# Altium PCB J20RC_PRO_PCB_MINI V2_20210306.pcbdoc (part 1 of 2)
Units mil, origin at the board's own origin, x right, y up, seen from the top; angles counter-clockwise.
Board outline 5082.94 x 4658.14 mil, 2 copper layers (Top Layer, Bottom Layer); 108 components, 96 nets, 409 pads, 123 vias.
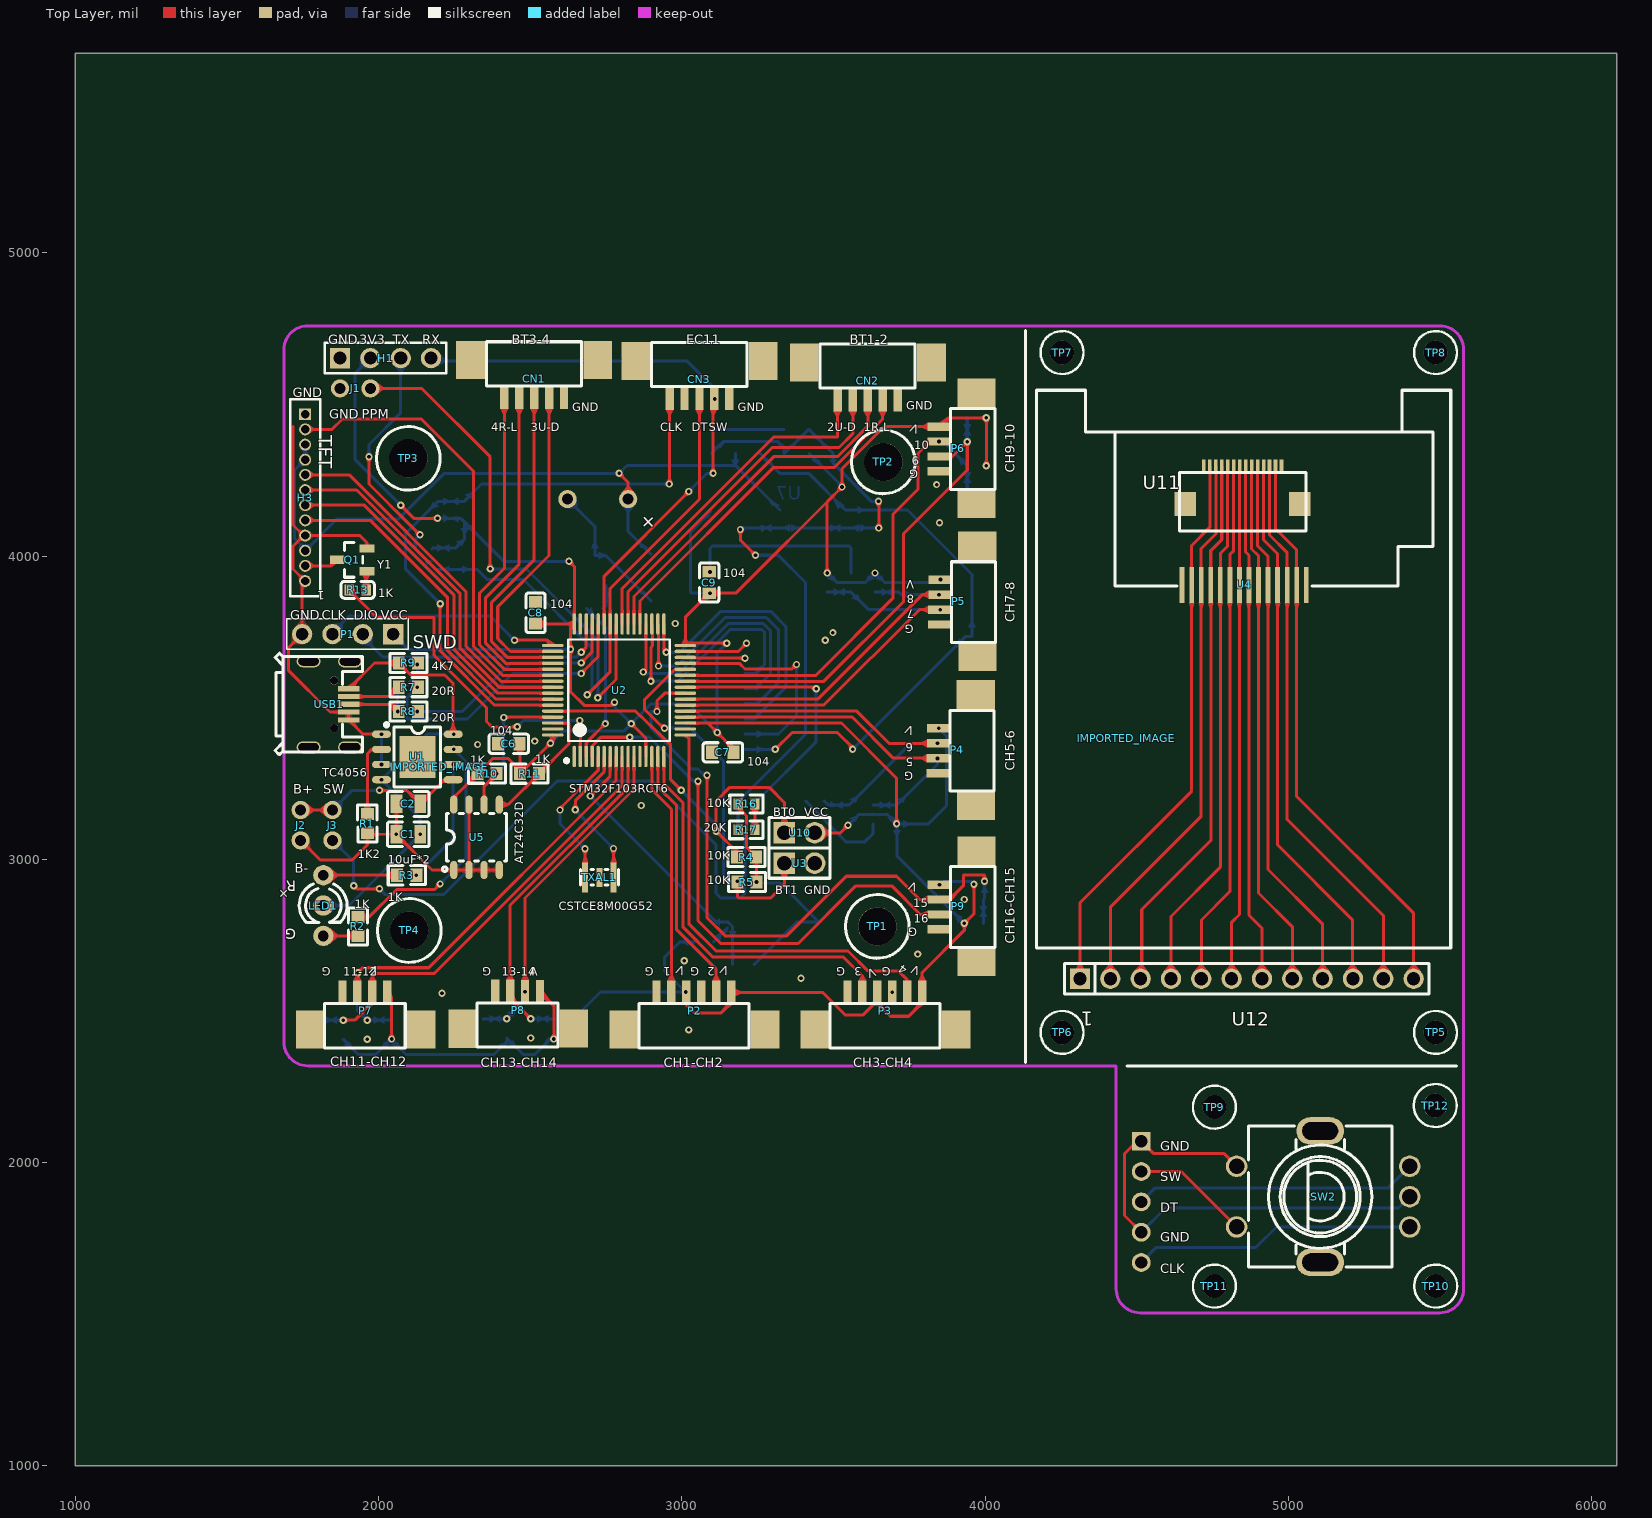
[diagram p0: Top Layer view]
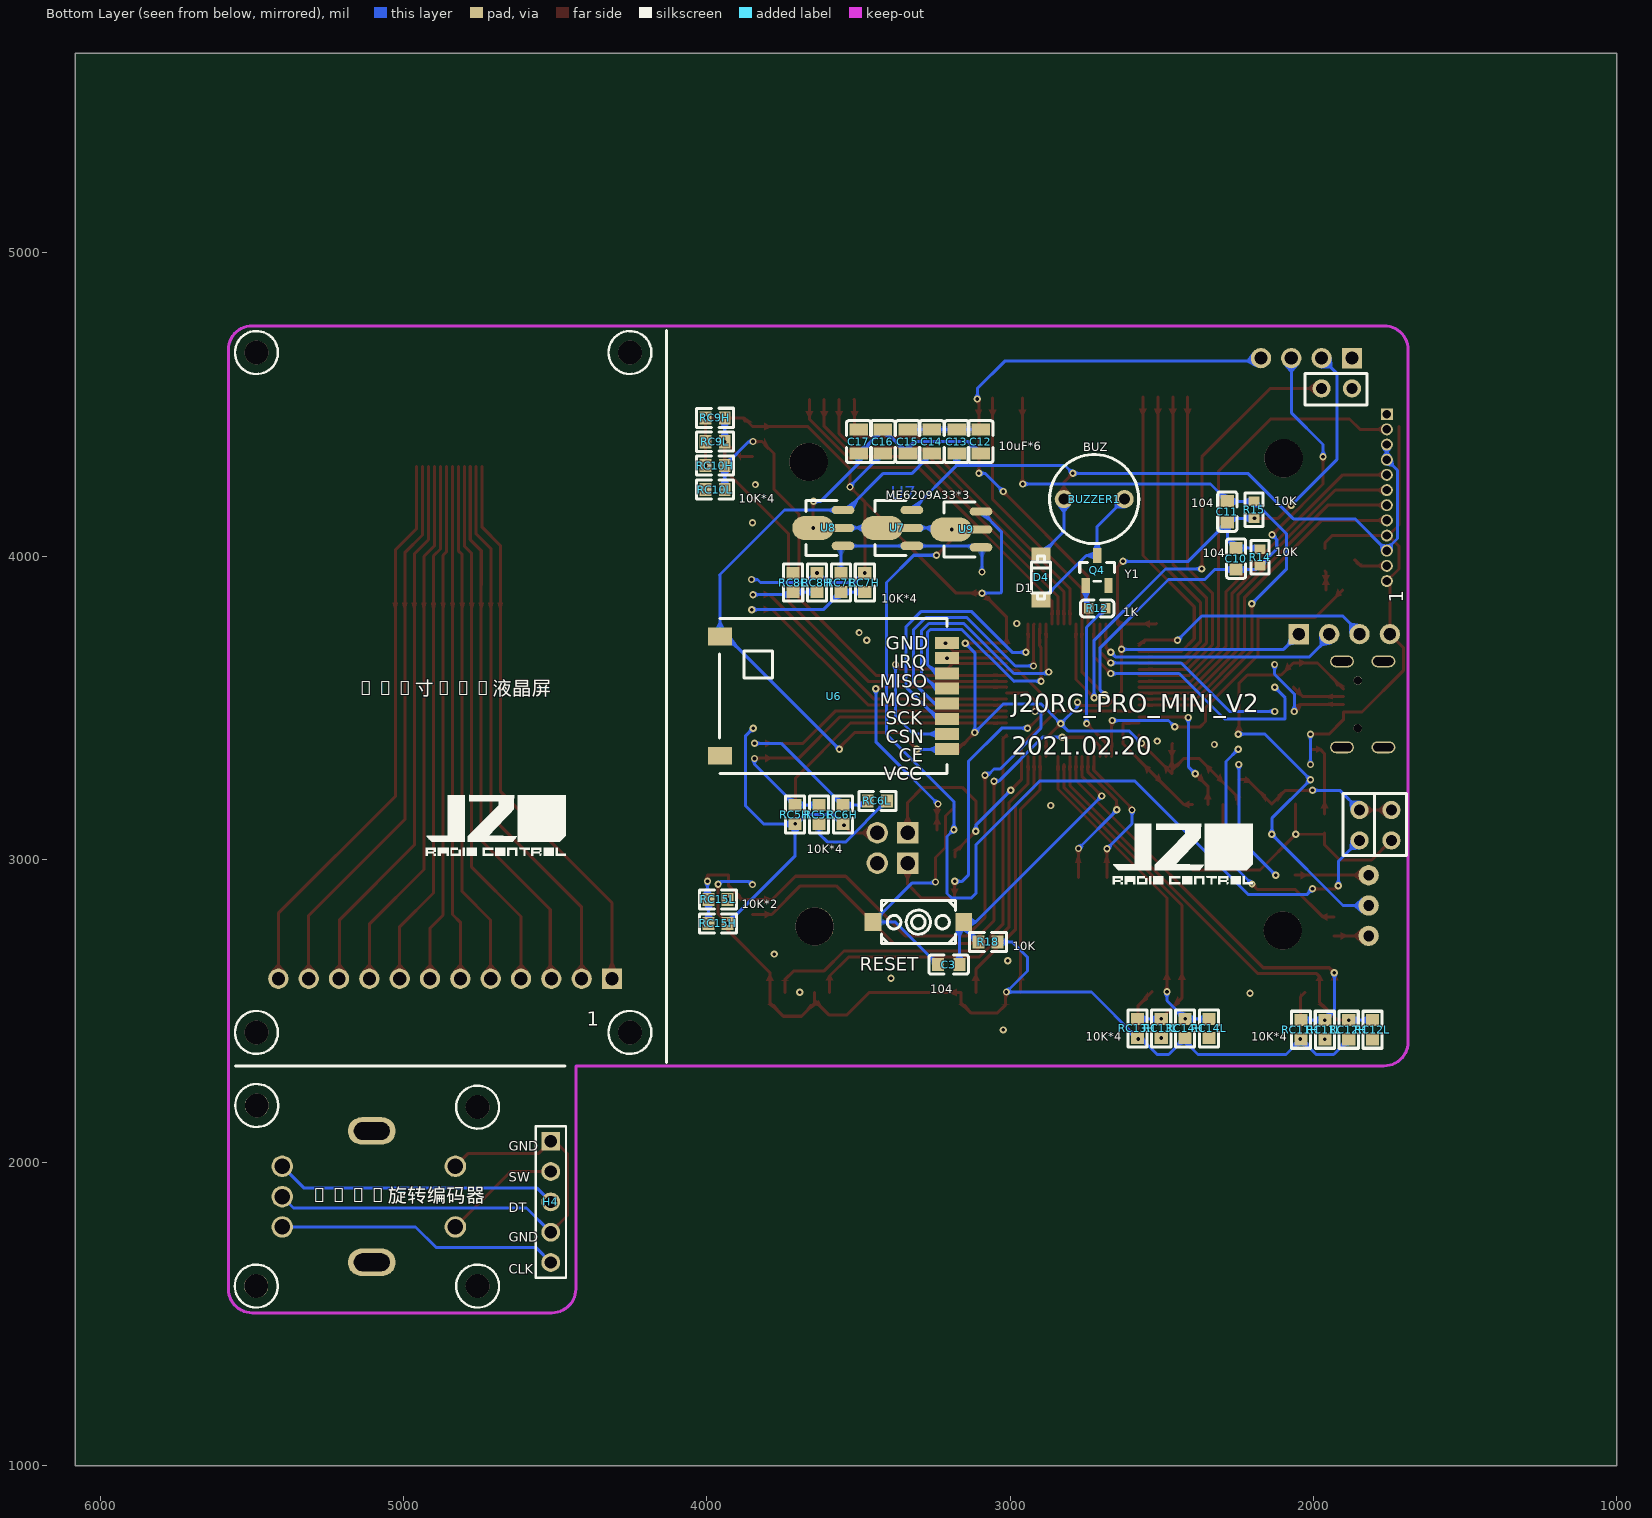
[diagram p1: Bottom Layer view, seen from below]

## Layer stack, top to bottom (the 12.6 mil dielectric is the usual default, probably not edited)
Top Layer: signal copper (thickness not stored)
Dielectric: dielectric 12.6, FR-4, Dk 4.8
Bottom Layer: signal copper (thickness not stored)

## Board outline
6082.94,1000 1000,1000 1000,5658.14 6082.94,5658.14

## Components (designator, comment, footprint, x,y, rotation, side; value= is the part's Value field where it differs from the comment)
BUZZER1 "CY-9650-5029" 3.3V蜂鸣器 2823.27,4187.75 r0 bottom
C1 "10uF" C0805#1 2098.27,3082.75 r180 top
C2 "10uF" C0805#1 2098.27,3182.75 r0 top
C3 "104" C0603#1 3202.95,2653.07 r180 bottom
C6 "104" C0603#2 2429.92,3381.37 r0 top
C7 "104" C0603#2 3135.43,3353.03 r0 top
C8 "104" C0603#2 2518.11,3812.87 r270 top
C9 "104" C0603#2 3090.55,3912.87 r270 top
C10 "104" C0603#1 2255.12,3991.61 r270 bottom
C11 "104" C0603#1 2284.25,4146.73 r270 bottom
C12 "10uF" C0805#2 3097.64,4377.44 r90 bottom
C13 "10uF" C0805#2 3176.38,4377.44 r90 bottom
C14 "10uF" C0805#2 3259.06,4377.44 r90 bottom
C15 "10uF" C0805#2 3337.8,4377.44 r90 bottom
C16 "10uF" C0805#2 3420.47,4377.44 r90 bottom
C17 "10uF" C0805#2 3499.21,4377.44 r90 bottom
CN1 "1.25T-5P" CONN-SMD_1.25T-5P 2513.27,4585.25 r0 top
CN2 "1.25T-5P" CONN-SMD_1.25T-5P 3613.27,4577.75 r0 top
CN3 "1.25T-5P" CONN-SMD_1.25T-5P 3058.27,4582.75 r0 top
D4 "1N5819" 1N5819-SOD123 2893.27,3947.75 r0 bottom
H1 "A2541WV-4P" HDR-TH_4P-P2.54-V 2023.27,4652.75 r0 top
H3 "1.27mm1*12P Straight Headers  Pins" HDR-TH_12P-P1.27-V 1758.27,4192.75 r270 top
H4 "HDR-TH_5P-P2.54-V" HDR-TH_5P-P2.54-V 4514.78,1870.81 r90 bottom
IMPORTED_IMAGE "IMPORTED_IMAGE" IMPORTED_IMAGE 2200,3305.15 r0 top
IMPORTED_IMAGE "IMPORTED_IMAGE" IMPORTED_IMAGE 4464.89,3399.2 r0 top
J1 "PPM接口" 2.54MM_2P 1873.27,4552.75 r270 top
J2 "电池" 2.54MM_2P 1743.27,3062.75 r0 top
J3 "PPM接口" 2.54MM_2P 1848.27,3062.75 r0 top
LED1 "5mm双色LED共阳极" 3MM双色LED共阳极 1818.27,2847.75 r270 top
P1 "SWD接口" 4P_2.54 1903.27,3737.75 r0 top
P2 "CH1-2" 1.25MM-6P 3138.56,2500.25 r180 top
P3 "CH3-4" 1.25MM-6P 3768.27,2500.25 r180 top
P4 "CH5-6" 1.25MM-4P 3908.27,3407.75 r270 top
P5 "CH7-8" 1.25MM-4P 3913.27,3897.75 r270 top
P6 "CH7-8" 1.25MM-4P 3910.77,4402.75 r270 top
P7 "CH5-6" 1.25MM-4P 2004.72,2500.27 r180 top
P8 "CH7-8" 1.25MM-4P 2508.27,2502.75 r180 top
P9 "CH5-6" 1.25MM-4P 3910.77,2892.75 r270 top
Q1 "SS8050" SOT-23(SOT-23-3)#1 1913.27,3987.75 r90 top
Q4 "SS8050" SOT-23(SOT-23-3)#2 2713.27,3952.75 r0 bottom
R1 "1.2k" R0603#1 1963.27,3117.75 r90 top
R2 "1k" R0603#1 1932.28,2779.01 r90 top
R3 "1k" R0603#1 2093.27,2947.75 r0 top
R4 "10k" R0603#1 3213.27,3007.75 r0 top
R5 "10k" R0603#1 3214.71,2925.35 r0 top
R7 "20R" R0603#1 2098.27,3567.75 r180 top
R8 "20R" R0603#1 2098.27,3487.75 r180 top
R9 "4.7k" R0603#1 2098.27,3647.75 r0 top
R10 "1k" R0603#1 2358.27,3282.75 r180 top
R11 "1k" R0603#1 2498.27,3282.75 r180 top
R12 "1k" C0603#3 2713.27,3827.75 r180 bottom
R13 "1k" C0603#4 1931.51,3888.42 r0 top
R14 "10k" R0603#2 2176.38,3995.55 r90 bottom
R15 "10k" R0603#2 2196.06,4153.03 r90 bottom
R16 "10k" R0603#3 3213.27,3182.75 r0 top
R17 "20k" R0603#3 3213.27,3097.75 r180 top
R18 "10k" R0603#4 3073.27,2727.75 r0 bottom
RC5H "10k" R0603#4 3709.29,3147.73 r270 bottom
RC5L "10k" R0603#4 3630.55,3147.73 r270 bottom
RC6H "10k" R0603#4 3551.81,3147.73 r270 bottom
RC6L "10k" R0603#4 3438.27,3192.75 r180 bottom
RC7H "10k" R0603#4 3479.53,3912.75 r90 bottom
RC7L "10k" R0603#4 3558.27,3912.75 r90 bottom
RC8H "10k" R0603#4 3637.01,3912.75 r90 bottom
RC8L "10k" R0603#4 3715.75,3912.75 r90 bottom
RC9H "10k" R0603#4 3972.75,4455.77 r0 bottom
RC9L "10k" R0603#4 3972.75,4377.03 r0 bottom
RC10H "10k" R0603#4 3972.75,4298.29 r0 bottom
RC10L "10k" R0603#4 3972.75,4219.55 r0 bottom
RC11H "10k" R0603#4 2041.29,2438.27 r270 bottom
RC11L "10k" R0603#4 1962.55,2438.27 r270 bottom
RC12H "10k" R0603#4 1883.81,2438.27 r270 bottom
RC12L "10k" R0603#4 1805.07,2438.27 r270 bottom
RC13H "10k" R0603#4 2580.75,2442.75 r270 bottom
RC13L "10k" R0603#4 2502.01,2442.75 r270 bottom
RC14H "10k" R0603#4 2423.27,2442.75 r270 bottom
RC14L "10k" R0603#4 2344.53,2442.75 r270 bottom
RC15H "10k" R0603#4 3963.27,2789.01 r180 bottom
RC15L "10k" R0603#4 3963.27,2867.75 r180 bottom
RESET "K2-3.6×6.1_SMD" KEY-SMD_2P-L6.2-W3.6-LS8.0 3302.97,2793.05 r180 bottom
SW2 "EC11" SW-TH_EC11XXXXXXXX 5114.78,1888.01 r90 top
TP1 "M3铜柱_LCEDA" M3铜柱_LCEDA 3644.88,2779.01 r0 top
TP2 "M3铜柱_LCEDA" M3铜柱_LCEDA 3664.57,4310.51 r0 top
TP3 "M3铜柱_LCEDA" M3铜柱_LCEDA 2098.42,4322.32 r0 top
TP4 "M3铜柱_LCEDA" M3铜柱_LCEDA 2101.57,2765.63 r0 top
TP5 "M2铜柱" M2铜柱 5485.23,2429.41 r0 top
TP6 "M2铜柱" M2铜柱 4253.73,2429.41 r0 top
TP7 "M2铜柱" M2铜柱 4253.74,4671.14 r0 top
TP8 "M2铜柱" M2铜柱 5485.23,4671.14 r0 top
TP9 "M2铜柱" M2铜柱 4756.12,2183.12 r0 top
TP10 "M2铜柱" M2铜柱 5485.82,1593.19 r0 top
TP11 "M2铜柱" M2铜柱 4756.12,1593.19 r0 top
TP12 "M2铜柱" M2铜柱 5484.24,2188.46 r0 top
TXAL1 "OSC-SMD_3P-L3.2-W1.3-P1.2-L" OSC-SMD_3P-L3.2-W1.3-P1.2-L 2728.34,2940.43 r0 top
U1 "TC4056A" SOP-8_L4.9-W3.9-P1.27-LS6.0-BL-EP 2128.27,3337.75 r270 top
U2 "STM32F103RCT6" LQFP-64_L10.0-W10.0-P0.50-LS12.0-BL 2793.27,3557.75 r0 top
U3 "插排1*2P2.54mm" 1*2P-P2.54插针 3388.27,2987.75 r0 top
U4 "1.8寸TFTLCD" 1.8_TFT_LCD 4854.36,3838.14 r180 top
U5 "AT24C32D" SOIC-8_L4.9-W3.9-P1.27-LS6.0-BL 2323.27,3072.75 r0 top
U6 "NRF24L01" NRF24L01 3208.27,3282.75 r180 bottom
U7 "ME6209A33PG" SOT-89-3_L4.5-W2.5-P1.50-LS4.2-BR 3373.27,4092.75 r0 bottom
U8 "ME6209A33PG" SOT-89-3_L4.5-W2.5-P1.50-LS4.2-BR 3600.56,4092.75 r0 bottom
U9 "ME6209A33PG" SOT-89-3_L4.5-W2.5-P1.50-LS4.2-BR 3145.56,4087.75 r0 bottom
U10 "插排1*2P2.54mm" 1*2P-P2.54插针 3388.27,3087.75 r0 top
U11 "1.8寸TFTLCD插座" FPC-0.5MM-14P-QCHF-SM-H2.0 4849.36,4233.14 r0 top
U12 "DIP-1X12P-2.54MM" DIP-1X12P-2.54MM 4962.99,2606.57 r0 top
USB1 "U-F-M5DD-Y-1" MICRO-USB-SMD_U-F-M5DD-Y-1 1837.8,3511.3 r180 top
? "" ? 2880.52,5033.35 r0 top

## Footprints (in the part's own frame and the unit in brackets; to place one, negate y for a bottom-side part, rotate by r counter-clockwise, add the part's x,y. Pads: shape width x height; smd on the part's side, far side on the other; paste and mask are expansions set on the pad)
1*2P-P2.54插针 [mm]
  rect 1.8x1.8 hole 1.2: 1(-1.27,0)
  round 1.8 hole 1.2: 2(1.27,0)
  silkscreen extent -2.54,-1.27 2.54,1.27
1.8_TFT_LCD [mm]
  rect 0.4x3 smd: 1(5.2,-1.7) 2(4.4,-1.7) 3(3.6,-1.7) 4(2.8,-1.7) 5(2,-1.7) 6(1.2,-1.7) 7(0.4,-1.7) 8(-0.4,-1.7) 9(-1.2,-1.7) 10(-2,-1.7) 11(-2.8,-1.7) 12(-3.6,-1.7) 13(-4.4,-1.7) 14(-5.2,-1.7)
  silkscreen extent -17.3,-18 17.4,28.7
1.25MM-4P [mm]
  rect 2.4x3.2 smd: 0(-3.457,1.544) 0(5.845,1.559)
  rect 0.7x2 smd: 1(-0.614,-1.545) 2(0.636,-1.545) 3(1.886,-1.559) 4(3.136,-1.559)
  silkscreen extent -2.12,-0.62 4.65,3.09
1.25MM-6P [mm]
  rect 2.4x3.2 smd: 0(-3.457,1.544) 0(8.362,1.559)
  rect 0.7x2 smd: 1(-0.614,-1.545) 2(0.636,-1.545) 3(1.886,-1.559) 4(3.136,-1.559) 5(4.386,-1.559) 6(5.636,-1.559)
  silkscreen extent -2.12,-0.62 7.1,3.09
1N5819-SOD123 [mil]
  rect 63x43.3 smd: 1(5,95) 2(5,-58.6)
  silkscreen extent -26,-53 36,89
2.54MM_2P [mil]
  round 60 hole 36: 1(0,0) 2(0,100)
3.3V蜂鸣器 [mil]
  round 60 hole 36: 1(0,0) 2(-200,0)
  silkscreen extent -247,-147 47,147
3MM双色LED共阳极 [mm]
  round 1.7 hole 0.9: 1(-2.54,0) 2(0,0) 3(2.54,0)
  silkscreen extent -1.82,-2.02 1.43,1.99
4P_2.54 [mil]
  rect 66.93x66.93 hole 39.36: 1(145,5)
  round 66.93 hole 39.36: 2(45,5) 3(-55,5) 4(-155,5)
  silkscreen extent -205,-45 195,55
C0603#1 [mm]
  rect 1x1.1 smd: 1(0.9,0) 2(-0.9,0)
  silkscreen extent -1.65,-0.8 1.65,0.8
C0603#2 [mm]
  rect 1x1.1 smd: 1(-0.9,0) 2(0.9,0)
  silkscreen extent -1.65,-0.8 1.65,0.8
C0603#3 [mm]
  rect 0.8x0.9 smd: 1(0.7,0) 2(-0.7,0)
  silkscreen extent -1.4,-0.72 1.4,0.7
C0603#4 [mm]
  rect 0.8x0.9 smd: 1(-0.7,0) 2(0.7,0)
  silkscreen extent -1.4,-0.7 1.4,0.72
C0805#1 [mm]
  rect 1x1.55 smd: 1(-1,0) 2(1,0)
  silkscreen extent -1.75,-1.04 1.75,1.04
C0805#2 [mm]
  rect 1x1.55 smd: 1(1,0) 2(-1,0)
  silkscreen extent -1.75,-1.04 1.75,1.04
CONN-SMD_1.25T-5P [mm]
  rect 2.4x3.2 smd: 0(-5.331,1.545) 0(5.331,1.546)
  rect 0.7x2 smd: 1(-2.5,-1.546) 2(-1.25,-1.546) 3(0,-1.546) 4(1.25,-1.546) 5(2.5,-1.546)
  silkscreen extent -4,-0.61 3.96,3.09
DIP-1X12P-2.54MM [mm]
  rect 1.7x1.7 hole 1.1: 1(-16.51,0)
  round 1.7 hole 1.1: 2(-13.97,0) 3(-11.43,0) 4(-8.89,0) 5(-6.35,0) 6(-3.81,0) 7(-1.27,0) 8(1.27,0) 9(3.81,0) 10(6.35,0) 11(8.89,0) 12(11.43,0)
  silkscreen extent -17.82,-1.27 12.7,1.27
FPC-0.5MM-14P-QCHF-SM-H2.0 [mm]
  rect 0.3x1.2 smd: 1(-3.25,1.575) 2(-2.75,1.575) 3(-2.25,1.575) 4(-1.75,1.575) 5(-1.25,1.575) 6(-0.75,1.575) 7(-0.25,1.575) 8(0.25,1.575) 9(0.75,1.575) 10(1.25,1.575) 11(1.75,1.575) 12(2.25,1.575) 13(2.75,1.575) 14(3.25,1.575)
  rect 1.8x2 smd: 15(-4.8,-1.575) 16(4.8,-1.575)
  silkscreen extent -5.3,-3.82 5.3,1.08
HDR-TH_4P-P2.54-V [mm]
  rect 1.7x1.7 hole 1.1: 1(-3.81,0)
  round 1.7 hole 1.1: 2(-1.27,0) 3(1.27,0) 4(3.81,0)
  silkscreen extent -5.08,-1.27 5.08,1.27
HDR-TH_5P-P2.54-V [mil]
  rect 62x62 hole 40.16: 1(200,0)
  round 62 hole 40.16: 2(100,0) 3(0,0) 4(-100,0) 5(-200,0)
  silkscreen extent -250,-50 250,50
HDR-TH_12P-P1.27-V [mm]
  rect 1x1 hole 0.7: 1(-6.985,0)
  round 1 hole 0.7: 2(-5.715,0) 3(-4.445,0) 4(-3.175,0) 5(-1.905,0) 6(-0.635,0) 7(0.635,0) 8(1.905,0) 9(3.175,0) 10(4.445,0) 11(5.715,0) 12(6.985,0)
  silkscreen extent -8.24,-1.25 8.25,1.25
IMPORTED_IMAGE [mil]
KEY-SMD_2P-L6.2-W3.6-LS8.0 [mm]
  rect 1.4x1.5 smd: 1(3.8,0) 2(-3.8,0)
  silkscreen extent -3.1,-1.8 3.1,1.8
LQFP-64_L10.0-W10.0-P0.50-LS12.0-BL [mm]
  oval 0.28x1.8 smd: 1(-3.75,-5.55) 2(-3.25,-5.55) 3(-2.75,-5.55) 4(-2.25,-5.55) 5(-1.75,-5.55) 6(-1.25,-5.55) 7(-0.75,-5.55) 8(-0.25,-5.55) 9(0.25,-5.55) 10(0.75,-5.55) 11(1.25,-5.55) 12(1.75,-5.55) 13(2.25,-5.55) 14(2.75,-5.55) 15(3.25,-5.55) 16(3.75,-5.55) 33(3.75,5.55) 34(3.25,5.55) 35(2.75,5.55) 36(2.25,5.55) 37(1.75,5.55) 38(1.25,5.55) 39(0.75,5.55) 40(0.25,5.55) 41(-0.25,5.55) 42(-0.75,5.55) 43(-1.25,5.55) 44(-1.75,5.55) 45(-2.25,5.55) 46(-2.75,5.55) 47(-3.25,5.55) 48(-3.75,5.55)
  oval 1.8x0.28 smd: 17(5.55,-3.75) 18(5.55,-3.25) 19(5.55,-2.75) 20(5.55,-2.25) 21(5.55,-1.75) 22(5.55,-1.25) 23(5.55,-0.75) 24(5.55,-0.25) 25(5.55,0.25) 26(5.55,0.75) 27(5.55,1.25) 28(5.55,1.75) 29(5.55,2.25) 30(5.55,2.75) 31(5.55,3.25) 32(5.55,3.75) 49(-5.55,3.75) 50(-5.55,3.25) 51(-5.55,2.75) 52(-5.55,2.25) 53(-5.55,1.75) 54(-5.55,1.25) 55(-5.55,0.75) 56(-5.55,0.25) 57(-5.55,-0.25) 58(-5.55,-0.75) 59(-5.55,-1.25) 60(-5.55,-1.75) 61(-5.55,-2.25) 62(-5.55,-2.75) 63(-5.55,-3.25) 64(-5.55,-3.75)
  silkscreen extent -4.55,-6.05 4.25,4.25
M2铜柱 [mm]
  round 2 hole 2 unplated: ""(0,0)
  silkscreen extent -1.8,-1.8 1.8,1.8
M3铜柱_LCEDA [mm]
  round 3.2 hole 3.2: 1(0,0)
  silkscreen extent -2.66,-2.67 2.67,2.67
MICRO-USB-SMD_U-F-M5DD-Y-1 [mm]
  rect 1.8x0.43 smd: 1(-1.626,-1.3) 2(-1.626,-0.65) 3(-1.626,0) 4(-1.626,0.65) 5(-1.626,1.3)
  oval 2x1 hole 0.7 slot 1.7 at 0 deg: 6(-1.735,3.599) 7(1.735,3.6) 8(-1.735,-3.599) 9(1.735,-3.6)
  round 0.7 hole 0.7 unplated: ""(-0.415,2) ""(-0.415,-2)
  silkscreen extent -2.77,-4.28 4.55,4.22
NRF24L01 [mm]
  rect 2x1.5 smd: 1(-19,1.5) 2(-19,11.5)
  rect 2x1 smd: 1(0,10.94) 2(0,2.05) 3(0,3.32) 4(0,4.59) 5(0,5.86) 6(0,7.13) 7(0,8.4) 8(0,9.67)
  silkscreen extent -19.05,0 0,13
OSC-SMD_3P-L3.2-W1.3-P1.2-L [mm]
  rect 0.5x2.5 smd: 1(-1.199,0) 3(1.199,0)
  rect 0.5x1.6 smd: 2(0,0)
  silkscreen extent -1.6,-0.65 1.6,0.65
R0603#1 [mm]
  rect 1x1.1 smd: 1(-0.8,0) 2(0.8,0)
  silkscreen extent -1.55,-0.8 1.55,0.81
R0603#2 [mm]
  rect 0.8x0.9 smd: 1(0.7,0) 2(-0.7,0)
  silkscreen extent -1.4,-0.76 1.4,0.75
R0603#3 [mm]
  rect 0.8x0.9 smd: 1(-0.7,0) 2(0.7,0)
  silkscreen extent -1.4,-0.75 1.4,0.76
R0603#4 [mm]
  rect 1x1.1 smd: 1(0.8,0) 2(-0.8,0)
  silkscreen extent -1.55,-0.81 1.55,0.8
SOIC-8_L4.9-W3.9-P1.27-LS6.0-BL [mm]
  oval 0.6x1.52 smd: 1(-1.905,-2.74) 2(-0.635,-2.74) 3(0.635,-2.74) 4(1.905,-2.74) 5(1.905,2.74) 6(0.635,2.74) 7(-0.635,2.74) 8(-1.905,2.74)
  silkscreen extent -2.86,-2.86 2.5,2
SOP-8_L4.9-W3.9-P1.27-LS6.0-BL-EP [mm]
  oval 0.6x1.6 smd: 1(-1.905,-3) 2(-0.635,-3) 3(0.635,-3) 4(1.905,-3) 5(1.905,3) 6(0.635,3) 7(-0.635,3) 8(-1.905,3)
  rect 3.5x3 smd: 9(0,0)
  silkscreen extent -2.84,-2.74 2.5,1.95
SOT-23(SOT-23-3)#1 [mm]
  rect 0.7x1.25 smd: 1(-0.95,-1.25) 2(0.95,-1.25) 3(0,1.25)
  silkscreen extent -1.46,-0.9 1.46,0.65
SOT-23(SOT-23-3)#2 [mm]
  rect 0.7x1.25 smd: 1(0.95,1.25) 2(-0.95,1.25) 3(0,-1.25)
  silkscreen extent -1.46,-0.65 1.46,0.9
SOT-89-3_L4.5-W2.5-P1.50-LS4.2-BR [mm]
  oval 1.9x0.7 smd: 1(-1.25,1.501) 3(-1.25,-1.501)
  oval 2.1x0.7 smd: 2(-1.151,0)
  oval 3.5x2 smd: 2(1.25,0)
  silkscreen extent -0.75,-2.3 1.85,2.3
SW-TH_EC11XXXXXXXX [mm]
  oval 2.3x4 hole 1.5 slot 3 at 90 deg: 6(5.5,0.25) 7(-5.5,0.25)
  round 1.8 hole 1.3: A(-2.54,-7.25) B(2.54,-7.25) C(0,-7.25) D(-2.54,7.25) E(2.54,7.25)
  silkscreen extent -5.9,-5.75 5.9,6.25
? [mil]

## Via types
v1: diameter 24, hole 12, Top Layer to Bottom Layer, 123 vias

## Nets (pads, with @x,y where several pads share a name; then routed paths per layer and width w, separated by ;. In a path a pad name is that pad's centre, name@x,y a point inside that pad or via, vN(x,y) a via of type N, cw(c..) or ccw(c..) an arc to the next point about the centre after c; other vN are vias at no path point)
1SL: R5.1 U2.28 U3.1 | length 1904.7
  Top Layer w10: v1@2941.57,3430.85 2876.57,3495.85 2876.57,3525.85 2975.37,3624.75 U2.28@3009.97,3624.75 ; R5.1@3183.27,2927.75 3183.27,2877.75 3188.27,2872.75 3293.27,2872.75 3338.27,2917.75 U3.1@3338.27,2987.75
  Bottom Layer w10: v1(3183.27,2927.76) 3158.27,2927.75 ; 3028.27,3432.75 v1(2943.27,3432.76) 3028.27,3432.75 ; 3028.27,3432.75 3138.27,3322.75 ; 3028.27,3432.75 3138.27,3322.75 ; 3138.27,2947.75 3138.27,3322.75 ; 3138.27,2947.75 3158.27,2927.75 ; 3138.27,2947.75 3138.27,3322.75 ; 3138.27,2947.75 3158.27,2927.75
2SL: R4.1 U2.60 U10.1 | length 1791
  Top Layer w10: v1@2998.27,3227.75 2963.27,3262.75 2963.27,3377.75 ; R4.1@3181.77,3007.75 3181.77,3024.25 3113.27,3092.75 3113.27,3192.75 3158.27,3237.75 3288.27,3237.75 3338.27,3187.75 U10.1@3338.27,3087.75 ; 2847.17,3488.85 2574.77,3488.85 2847.17,3488.85 ; 2847.17,3488.85 2963.27,3377.75 ; 2847.17,3488.85 2963.27,3377.75
  Bottom Layer w10: v1(2998.27,3227.76) 3113.27,3112.75 v1(3113.27,3092.76)
+5V: C1.1 LED1.2 R9.1 U1.4 U1.8 USB1.1 | length 1524.7
  Top Layer w10: USB1.1@1901.81,3562.5 1987.07,3647.75 2066.77,3647.75 2106.77,3607.75 2218.27,3607.75 2246.37,3579.65 U1.8@2246.37,3412.75
  Bottom Layer w10: LED1.2@1818.27,2847.75 1902.64,2847.75 v1(2137.64,3082.76) 2137.64,3135.27 2010.16,3262.75 2160.16,3412.75 v1(2248.27,3412.76)
  other v1: 2010.16,3262.76
BAT+: C12.2 C15.2 C16.1 C17.2 J3.1 R17.2 U7.2 U8.2 U9.2 | length 4619.3
  Top Layer w10: v1(1918.27,2912.76) 1928.27,2902.75 v1(2003.27,2902.76) ; v1(3193.27,4087.76) 3193.27,4052.75 v1(3243.27,4002.76) ; v1(3648.82,4180.59) 3649.76,4179.64 v1(3649.76,4092.76)
  Bottom Layer w10: J3.1@1848.27,3062.75 1918.27,2992.75 v1(1918.27,2912.76) ; v1@2003.27,2902.75 2022.27,2883.75 2214.27,2883.75 2588.27,3257.75 2903.27,3257.75 3113.27,3047.75 3113.27,2887.75 3128.27,2872.75 3193.27,2872.75 3208.27,2887.75 3208.27,3075.15 v1@3185.67,3097.75 ; C12.2@3097.67,4338.05 3137.07,4377.45 3317.57,4377.45 3337.77,4357.25 3337.77,4338.05 3416.57,4416.85 C16.1@3420.47,4416.81 3499.27,4338.05 3499.27,4306.55 3625.17,4180.55 v1@3648.87,4180.55 ; v1(3185.71,3097.76) 3185.71,3190.2 3403.27,3407.75 3408.27,3412.75 3408.27,3912.75 3318.27,4002.75 v1(3243.27,4002.76) ; U9.2@3194.77,4087.75 3199.77,4092.75 U8.2@3649.77,4092.75
BEEPER: R12.1 U2.3 | length 540.6
  Top Layer w10: U2.3@2684.97,3339.25 2684.97,3384.45 v1@2748.27,3447.75
  Bottom Layer w10: R12.1@2685.67,3827.75 2748.27,3765.15 v1@2748.27,3447.75
  other v1: 2748.27,3447.76
BM_CLK: C11.2 CN3.1 R15.1 U2.59 | length 2101.2
  Top Layer w10: v1@2203.27,3842.75 2203.27,3687.75 2382.47,3508.55 U2.59@2574.77,3508.54 ; v1@2958.27,4237.75 2959.87,4237.75 CN3.1@2959.87,4521.85
  Bottom Layer w10: v1@2203.27,3842.75 2089.77,3956.25 2089.77,4074.25 2196.07,4180.55 2282.67,4180.55 2284.27,4182.15 2339.87,4237.75 v1@2958.27,4237.75
  other v1: 2203.27,3842.76 2958.27,4237.76
CH1: P2.5 U2.14 | length 804.2
  Top Layer w10: U2.14@2901.57,3339.25 2901.57,3229.45 2965.87,3165.15 P2.5@2965.88,2561.61
CH1_LEFT: CN2.4 U2.37 | length 1189.3
  Top Layer w10: U2.37@2862.17,3776.25 2862.17,3851.65 3303.27,4292.75 3503.27,4292.75 3662.47,4451.95 CN2.4@3662.47,4516.85
CH1_RIGHT: CN2.3 U2.38 | length 1182.9
  Top Layer w10: U2.38@2842.47,3776.25 2842.47,3866.95 3303.27,4327.75 3513.27,4327.75 3613.27,4427.75 CN2.3@3613.27,4516.85
CH2: P2.2 U2.15 | length 857.9
  Top Layer w10: U2.15@2921.17,3339.25 2921.17,3239.85 2983.27,3177.75 2983.27,2767.75 3113.57,2637.45 P2.2@3113.57,2561.05
CH2_DOWN: CN2.2 U2.39 | length 1176.5
  Top Layer w10: U2.39@2822.77,3776.25 2822.77,3882.25 3298.27,4357.75 3518.27,4357.75 3564.07,4403.55 CN2.2@3564.07,4516.85
CH2_UP: CN2.1 U2.40 | length 1158.5
  Top Layer w10: U2.40@2803.07,3776.25 2803.07,3892.55 3303.27,4392.75 3513.27,4392.75 3513.27,4515.35 CN2.1@3514.87,4516.85
CH3: P3.5 U2.16 | length 1300.7
  Top Layer w10: U2.16@2940.87,3339.25 2940.87,3250.15 3003.27,3187.75 3003.27,2777.75 3103.27,2677.75 3533.27,2677.75 3595.57,2615.45 P3.5@3595.59,2561.61
CH3_DOWN: CN1.4 U2.50 | length 1065.6
  Top Layer w10: CN1.4@2562.47,4524.35 2562.47,4001.95 2393.27,3832.75 2393.27,3727.75 2435.37,3685.65 U2.50@2574.77,3685.65
CH3_UP: CN1.3 U2.51 | length 1087.5
  Top Layer w10: CN1.3@2513.27,4524.35 2513.27,3987.75 2373.27,3847.75 2373.27,3717.75 2424.97,3666.05 U2.51@2574.77,3666.02
CH4: P3.2 U2.17 | length 1465.5
  Top Layer w10: U2.17@3011.77,3410.11 3023.27,3398.65 3023.27,2787.75 3113.27,2697.75 3548.27,2697.75 3613.27,2632.75 3713.27,2632.75 3743.27,2602.75 P3.2@3743.27,2561.05
CH4_LEFT: CN1.2 U2.52 | length 1106.5
  Top Layer w10: CN1.2@2464.07,4524.35 2464.07,3973.55 2353.27,3862.75 2353.27,3712.75 2419.67,3646.35 U2.52@2574.77,3646.33
CH4_RIGHT: CN1.1 U2.53 | length 1125.5
  Top Layer w10: CN1.1@2414.87,4524.35 2414.87,3959.35 2333.27,3877.75 2333.27,3707.75 2414.37,3626.65 U2.53@2574.77,3626.65
CH5: P4.3 RC5H.2 RC5L.2 U2.20 | length 1179
  Top Layer w10: U2.20@3011.77,3469.15 3561.87,3469.15 3697.47,3333.55 P4.3@3846.91,3333.5
  Bottom Layer w10: RC5L.2@3630.57,3179.25 RC5H.2@3709.29,3179.22 3843.27,3313.25 v1@3843.27,3332.75
  other v1: 3843.27,3332.76
CH6: P4.2 RC6H.2 RC6L.2 U2.21 | length 1343
  Top Layer w10: U2.21@3011.77,3488.85 3577.17,3488.85 3683.27,3382.75 P4.2@3847.47,3382.75
  Bottom Layer w10: RC6L.2@3469.77,3192.75 3483.27,3179.25 RC6H.2@3551.81,3179.22 3755.37,3382.75 v1@3843.27,3382.75
  other v1: 3843.27,3382.76
CH7: P5.3 RC7H.2 RC7L.2 U2.22 | length 1366.3
  Top Layer w10: U2.22@3011.77,3508.54 3467.47,3508.55 3783.97,3823.45 P5.3@3851.87,3823.45
  Bottom Layer w10: RC7H.2@3479.57,3881.25 3558.27,3881.25 3616.07,3823.45 v1@3851.87,3823.45
  other v1: 3851.87,3823.46
CH8: P5.2 RC8H.2 RC8L.2 U2.23 | length 1198.2
  Top Layer w10: U2.23@3011.77,3528.22 3448.77,3528.25 3793.27,3872.75 P5.2@3852.47,3872.75
  Bottom Layer w10: RC8H.2@3636.97,3881.25 3715.77,3881.25 3724.27,3872.75 v1@3848.27,3872.75
  other v1: 3848.27,3872.76
CH9: P6.3 RC9H.2 RC9L.2 U2.26 | length 1632.9
  Top Layer w10: U2.26@3011.77,3587.25 3468.27,3587.25 3731.47,3850.45 3731.47,4074.25 3941.27,4284.05 v1(3941.26,4377.04) 3892.77,4328.55 P6.3@3849.41,4328.5
  Bottom Layer w10: v1(3941.26,4377.04) RC9H.2@3941.27,4455.75
CH10: P6.2 RC10H.2 RC10L.2 U2.27 | length 1593.4
  Top Layer w10: U2.27@3011.77,3606.95 3442.47,3606.95 3696.07,3860.55 3696.07,4137.25 3778.77,4219.95 3778.77,4338.05 3818.37,4377.75 P6.2@3849.97,4377.75
  Bottom Layer w10: v1@3848.27,4377.75 3861.77,4377.75 3941.27,4298.25 RC10L.2@3941.27,4219.55
  other v1: 3848.27,4377.76
CH11: P7.3 RC11H.2 RC11L.2 U2.8 | length 1506.8
  Top Layer w10: P7.3@1930.47,2561.63 1930.47,2625.25 1948.07,2642.75 2166.17,2642.75 2783.47,3260.05 U2.8@2783.47,3339.25
  Bottom Layer w10: v1(1931.47,2626.25) 1931.47,2500.85 1962.57,2469.75 RC11H.2@2041.27,2469.75
  other v1: 1962.55,2469.77
CH12: P7.2 RC12H.2 RC12L.2 U2.9 | length 1464.4
  Top Layer w10: v1@1883.77,2469.75 1921.47,2469.75 1979.67,2528.05 1979.67,2561.05 1979.67,2613.05 1989.77,2623.15 2183.27,2623.15 2803.07,3242.95 U2.9@2803.07,3339.25
  Bottom Layer w10: RC12L.2@1805.07,2469.75 RC12H.2@1883.77,2469.75
  other v1: 1883.81,2469.77
CH13: P8.3 RC13H.2 RC13L.2 U2.10 | length 1106.6
  Top Layer w10: P8.3@2434.02,2564.11 2433.97,2848.45 2823.27,3237.75 U2.10@2823.27,3312.75 ; P8.3@2434.07,2564.15 2434.07,2542.25 v1@2501.97,2474.25
  Bottom Layer w10: RC13L.2@2502.01,2474.25 RC13H.2@2580.77,2474.25
  other v1: 2502.01,2474.26
CH14: P8.2 RC14H.2 RC14L.2 U2.11 | length 1117.3
  Top Layer w10: P8.2@2483.27,2563.55 2483.27,2872.75 2842.47,3231.95 U2.11@2842.47,3339.25
  Bottom Layer w10: RC14L.2@2344.57,2474.25 RC14H.2@2423.27,2474.25 2483.27,2534.25 v1@2483.27,2563.55
  other v1: 2423.27,2474.26 2483.27,2563.56
CH15: P9.2 RC15H.2 RC15L.2 U2.24 | length 2199.9
  Top Layer w10: v1@2918.27,3487.75 2918.27,3522.75 2943.47,3547.95 U2.24@3011.77,3547.91 ; v1@3083.27,3277.75 3083.27,2807.75 3143.27,2747.75 3345.87,2747.75 3542.57,2944.35 3707.87,2944.35 3784.47,2867.75 3849.97,2867.75 3883.27,2867.75 3928.27,2912.75 3928.27,2947.75 3998.27,2947.75 v1@3998.27,2927.75
  Bottom Layer w10: v1(2918.27,3487.76) 2898.27,3487.75 2898.27,3432.75 3033.27,3297.75 3053.27,3297.75 3073.27,3277.75 v1(3083.27,3277.76) ; RC15H.2@3994.76,2789.01 3994.77,2867.75 3998.27,2871.25 v1@3998.27,2927.75
  other v1: 3998.27,2927.76
CH16: P9.3 U2.4 | length 1860.4
  Top Layer w10: U2.4@2704.67,3339.25 2704.67,3374.15 2733.27,3402.75 v1@2828.27,3402.75 ; v1@3053.27,3257.75 3053.27,2797.75 3128.27,2722.75 3383.87,2722.75 3573.97,2912.85 3692.17,2912.85 3786.47,2818.55 P9.3@3849.41,2818.5
  Bottom Layer w10: v1(2828.27,3402.76) 2893.27,3402.75 3038.27,3257.75 v1(3053.27,3257.76)
CN4_1: H4.5 SW2.A | length 933.9
  Bottom Layer w10: H4.5@4514.78,1670.81 4564.77,1720.81 4893.37,1720.81 4960.57,1788.01 SW2.A@5400.22,1788.01
CN4_3: H4.3 SW2.B | length 933.9
  Bottom Layer w10: H4.3@4514.78,1870.81 4559.77,1915.81 5327.97,1915.81 SW2.B@5400.22,1988.01
CN4_4: H4.2 SW2.D | length 390.3
  Top Layer w10: H4.2@4514.78,1970.81 4646.58,1970.81 SW2.D@4829.37,1788.01
CN4_5: H4.1 H4.4 SW2.C SW2.E | length 1636.7
  Top Layer w10: H4.4@4514.78,1770.81 4459.68,1825.9 4459.68,2029.7 4500.68,2070.8 H4.1@4514.78,2070.81 4554.78,2030.8 4786.58,2030.8 SW2.E@4829.38,1988
  Bottom Layer w10: H4.4@4514.78,1770.81 4594.77,1850.81 5362.97,1850.81 SW2.C@5400.22,1888.01
D4_1: BUZZER1.2 D4.1 Q4.3 | length 469.9
  Bottom Layer w10: BUZZER1.2@2623.27,4187.75 2713.27,4097.75 2713.27,4001.95 2749.07,4001.95 D4.1@2898.27,3852.75
EEPROM_SCL: R10.1 U2.61 U5.6 | length 476.7
  Top Layer w10: U5.6@2348.27,3180.63 2348.27,3241.25 R10.1@2389.77,3282.75 ; v1@2412.57,3467.95 2413.77,3469.15 U2.61@2574.77,3469.15
  Bottom Layer w10: v1(2389.76,3282.76) 2412.6,3305.59 v1(2412.6,3467.99)
EEPROM_SDA: R11.1 U2.62 U5.5 | length 433.8
  Top Layer w10: U5.5@2398.27,3180.63 2427.67,3180.65 2529.77,3282.75 2628.27,3381.25 2628.27,3447.75 2626.57,3449.45 U2.62@2574.77,3449.45
GND: C1.2 C2.1 C3.2 C6.1 C7.1 C8.1 C9.1 C12.1 C13.1 C14.1 C15.1 C17.1 CN1.5 CN2.5 CN3.2 CN3.5 H1.1 H3.1 H3.9 H3.12 J1.1 J2.1 P1.4 P2.3 P2.6 P3.3 P3.6 P4.4 P5.4 P6.4 P7.4 P8.4 P9.4 Q1.2 Q4.2 R1.1 R4.2 R5.2 R16.1 RC5L.1 RC6L.1 RC7L.1 RC8L.1 RC9L.1 RC10L.1 RC11L.1 RC12L.1 RC13L.1 RC14L.1 RC15L.1 RESET.2 TXAL1.2 U1.1 U1.3 U1.9 U2.12 U2.18 U2.31 U2.47 U2.63 U3.2 U5.1 U5.2 U5.3 U5.4 U5.7 U6.1 U7.1 U8.1 U9.1 USB1.4 USB1.5 | length 5014
  Top Layer w10: 1718.27,4427.75 1718.27,4102.75 H3.9@1753.27,4067.75 ; J2.1@1743.27,3062.75 1808.27,2997.75 1913.27,2997.75 1963.27,3047.75 R1.1@1963.27,3086.25 ; USB1.5@1901.81,3460.1 1949.17,3412.75 U1.1@2010.17,3412.75 ; USB1.5@1902.27,3461.55 1901.77,3462.05 1901.77,3485.65 1840.37,3485.65 1703.97,3622.05 1703.97,3698.45 1748.27,3742.75 1748.27,3907.76 H3.12@1758.27,3917.75 1718.27,3957.76 1718.27,4032.75 H3.9@1753.27,4067.76 ; Q1.2@1962.47,4025.15 1962.47,4043.55 1938.27,4067.75 1758.27,4067.75 H3.9@1753.27,4067.76 ; R1.1@1963.27,3083.25 C1.2@2058.87,3082.75 ; C2.1@2058.87,3182.75 C1.2@2058.87,3082.75 ; U5.1@2250.07,2964.85 U5.4@2398.27,2964.85 ; U5.7@2298.27,3180.63 2298.27,2964.85 2176.77,2964.85 C1.2@2058.87,3082.75 ; U2.31@3011.77,3685.7 3186.17,3685.75 v1@3213.27,3712.75 ; R16.1@3185.67,3182.75 3185.67,3170.35 3213.27,3142.75 3213.27,3039.25 3244.77,3007.75 3246.17,3006.35 R5.2@3246.17,2925.35
  Bottom Layer w10: v1@2010.16,3312.75 v1@2010.16,3412.75 ; v1@3093.27,3947.75 3093.27,4025.55 3096.37,4028.65 3101.37,4033.65 3551.37,4033.65 3558.27,4026.75 RC7L.1@3558.27,3944.25 ; C12.1@3097.67,4416.85 C15.1@3337.8,4416.81 ; C3.2@3238.37,2653.05 3378.37,2793.05 RESET.2@3452.57,2793.05 ; v1@3253.27,2922.75 3322.87,2922.75 RESET.2@3452.57,2793.05 ; RC6L.1@3408.27,3192.75 3541.77,3057.75 3603.27,3057.75 3630.27,3084.75 RC5L.1@3630.27,3116.25 ; RESET.2@3473.07,2813.57 RESET.2@3452.57,2793.05
  other v1: 1962.55,2406.78 2502.01,2411.26 3023.27,2437.76 2209.45,2558.54 3694.02,2561.62 3393.27,2607.76 3008.27,2665.55 3778.27,2687.76 3931.78,2867.76 3246.21,2925.36 2058.9,3082.76 2866.14,3177.44 2010.16,3312.76 2326.77,3379.01 2514.96,3390.04 2010.16,3412.76 3213.27,3712.76 3473.27,3722.76 3498.27,3747.76 2978.27,3777.76 3093.27,3947.76 3849.61,4109.72 3840.16,4235.7
LCD_A0: H3.7 U2.57 | length 1178.7
  Top Layer w10: H3.7@1758.27,4167.75 1953.27,4167.75 2248.27,3872.75 2248.27,3692.75 2393.07,3547.95 U2.57@2574.77,3547.91
LCD_CS: H3.2 U2.54 | length 1519
  Top Layer w10: H3.2@1758.27,4417.75 1846.57,4417.75 1881.07,4452.25 2140.97,4452.25 2313.27,4279.95 2313.27,3702.75 2409.07,3606.95 U2.54@2574.77,3606.95
LCD_LED: R13.1 U2.2 | length 1174
  Top Layer w10: R13.1@1903.95,3888.42 1994.57,3797.75 2183.27,3797.75 2183.27,3672.75 2355.87,3500.15 2355.87,3454.65 2373.27,3437.25 v1@2457.47,3437.25 ; v1@2663.27,3457.75 2665.37,3455.75 U2.2@2665.37,3339.25
  Bottom Layer w10: v1(2457.48,3437.28) 2477.95,3457.76 v1(2663.27,3457.76)
LCD_LED-: H3.11 Q1.3 | length 114.1
  Top Layer w10: H3.11@1758.27,3967.75 1844.07,3967.75 Q1.3@1864.07,3987.75
LCD_RST: H3.8 U2.58 | length 1163.2
  Top Layer w10: H3.8@1758.27,4117.75 1973.27,4117.75 2228.27,3862.75 2228.27,3687.75 2387.77,3528.25 U2.58@2574.77,3528.22
LCD_SCK: H3.5 U2.55 | length 1203.8
  Top Layer w10: H3.5@1758.27,4267.75 1903.27,4267.75 2288.27,3882.75 2288.27,3702.75 2403.77,3587.25 U2.55@2574.77,3587.25
LCD_SDA: H3.6 U2.56 | length 1191.3
  Top Layer w10: H3.6@1758.27,4217.75 1928.27,4217.75 2268.27,3877.75 2268.27,3697.75 2398.47,3567.55 U2.56@2574.77,3567.55
NRF_CE: U2.29 U6.3 | length 745
  Top Layer w10: U2.29@3011.77,3646.33 3189.67,3646.35 3208.27,3627.75 3363.27,3627.75 v1@3378.27,3642.75
  Bottom Layer w10: U6.3@3208.27,3413.45 3318.97,3413.45 3378.27,3472.75 v1@3378.27,3642.75
  other v1: 3378.27,3642.76
NRF_CSN: U2.33 U6.4 | length 1758.6
  Top Layer w10: U2.33@2940.87,3776.25 2940.87,3690.15 v1@2948.27,3682.75
  Bottom Layer w10: v1@2943.27,3687.75 v1(2948.27,3682.76) 2992.67,3682.15 3128.27,3817.75 ; 2993.27,3682.75 3128.27,3817.75 ; 3128.27,3817.75 3293.27,3817.75 ; 3128.27,3817.75 3293.27,3817.75 ; U6.4@3238.97,3463.45 3208.27,3463.45 U6.4@3238.97,3463.45 ; U6.4@3238.97,3463.45 3343.27,3567.75 ; U6.4@3238.97,3463.45 3343.27,3567.75 ; 3293.27,3817.75 3343.27,3767.75 ; 3293.27,3817.75 3343.27,3767.75 ; 3343.27,3567.75 3343.27,3767.75 ; 3343.27,3567.75 3343.27,3767.75
NRF_IRQ: U2.30 U6.8 | length 197.6
  Top Layer w10: U2.30@3011.77,3666.02 3014.37,3663.45 v1@3208.27,3663.45
  other v1: 3208.27,3663.47
NRF_MISO: U2.35 U6.7 | length 821
  Top Layer w10: v1@2898.27,3587.75 2898.27,3696.65 2903.27,3707.75 U2.35@2901.57,3776.25
  Bottom Layer w10: v1@2898.27,3587.75 2987.37,3587.35 3159.37,3757.75 3263.27,3757.75 3273.27,3747.75 3273.27,3642.75 3243.97,3613.45 U6.7@3208.27,3613.45
  other v1: 2898.27,3587.76
NRF_MOSI: U2.36 U6.6 | length 908.3
  Top Layer w10: v1@2873.27,3617.75 2881.87,3626.35 U2.36@2881.87,3776.25
  Bottom Layer w10: v1@2873.27,3617.75 2878.27,3612.75 2988.27,3612.75 3153.27,3777.75 3268.27,3777.75 3293.27,3752.75 3293.27,3612.75 3243.97,3563.45 U6.6@3208.27,3563.45
  other v1: 2873.27,3617.76
NRF_SCK: U2.34 U6.5 | length 930.9
  Top Layer w10: U2.34@2921.17,3776.25 2923.27,3774.25 v1@2923.27,3637.75
  Bottom Layer w10: v1@2923.27,3637.75 2983.27,3637.75 3138.27,3792.75 3143.27,3797.75 3278.27,3797.75 3283.27,3792.75 3318.27,3757.75 3318.27,3742.75 3318.27,3582.75 3248.97,3513.45 U6.5@3208.27,3513.45
  other v1: 2923.27,3637.76
PPM: J1.2 U2.41 | length 1768.7
  Top Layer w10: J1.2@1973.27,4552.75 2142.77,4552.75 2368.27,4327.25 v1@2368.27,3957.75 ; v1@2723.27,3532.75 2783.47,3592.95 U2.41@2783.47,3776.25
  Bottom Layer w10: v1(2368.27,3957.76) 2488.27,3957.75 2723.27,3722.75 v1(2723.27,3532.76)
Q1_1: Q1.1 R13.2 | length 63.3
  Top Layer w10: R13.2@1959.07,3888.42 1959.07,3946.95 Q1.1@1962.47,3950.35
R2_1: LED1.3 R2.1 | length 114.1
  Top Layer w10: LED1.3@1818.27,2747.75 1818.47,2747.55 R2.1@1932.28,2747.52
R3_1: LED1.1 R3.1 | length 243.5
  Top Layer w10: LED1.1@1818.27,2947.75 R3.1@2061.77,2947.75
R12_2: Q4.1 R12.2 | length 79.9
  Bottom Layer w10: R12.2@2740.87,3827.75 2750.67,3837.55 Q4.1@2750.67,3903.55
RX_BM_SW: CN3.4 H1.4 U2.43 | length 1919.3
  Top Layer w10: U2.43@2744.07,3776.25 2744.07,3933.55 v1@3023.27,4212.75 ; v1@3103.27,4272.75 3103.27,4517.65 CN3.4@3107.47,4521.85
  Bottom Layer w10: H1.4@2173.27,4652.75 2183.27,4642.75 3018.27,4642.75 3108.27,4552.75 v1(3108.27,4517.76) ; v1@3023.27,4212.75 3083.27,4272.75 v1@3103.27,4272.75
  other v1: 3023.27,4212.76 3103.27,4272.76
S$39: 
S$50: 
S$51: 
S$52: 
S$63: 
S$65: 
S$68: 
S$11530: 
S$11535: 
SWCLK: P1.3 U2.49 | length 794.6
  Top Layer w10: v1@2448.27,3722.75 2557.37,3722.75 U2.49@2574.77,3705.35
  Bottom Layer w10: P1.3@1848.27,3742.75 1848.27,3747.75 1903.27,3802.75 2368.27,3802.75 v1(2448.27,3722.76)
SWDIO: P1.2 U2.46 | length 863.6
  Top Layer w10: v1@2668.27,3682.75 2684.97,3699.45 U2.46@2684.97,3776.25
  Bottom Layer w10: P1.2@1948.27,3742.75 1948.27,3732.75 2013.27,3667.75 2653.27,3667.75 v1(2668.27,3682.76)
TX_BM_DT: C10.1 CN3.3 H1.3 R14.2 U2.42 | length 3041.4
  Top Layer w10: 2103.27,4102.75 1968.51,4237.51 ; v1(2137.01,4070.35) 2135.68,4070.35 1968.51,4237.52 ; v1@2688.27,3542.75 2763.77,3618.25 2763.77,3776.25 2763.77,3893.25 3058.27,4187.75 CN3.3@3058.27,4521.85 ; 1968.51,4237.51 v1(1968.51,4327.83) 1968.51,4237.52
  Bottom Layer w10: v1(1968.51,4327.83) 1968.51,4367.99 2073.27,4472.75 H1.3@2073.27,4652.75 ; v1(2137.01,4070.35) 2121.27,4054.65 2121.27,4023.05 2176.37,3967.95 2188.17,3956.15 2255.17,3956.15 2324.87,3956.15 2358.27,3922.75 2478.27,3922.75 2703.27,3697.75 2703.27,3557.75 v1@2688.27,3542.75
  other v1: 2688.27,3542.76
U1_2: R1.2 U1.2 | length 251.6
  Top Layer w10: R1.2@1963.27,3149.25 1963.27,3347.75 1978.27,3362.75 U1.2@2010.17,3362.75
U1_5: C2.2 J2.2 J3.2 U1.5 | length 581.8
  Top Layer w10: J2.2@1743.27,3162.75 J3.2@1848.27,3162.75 ; v1@2003.27,3227.75 2092.67,3227.75 2137.67,3182.75 2217.67,3262.75 U1.5@2246.37,3262.75
  Bottom Layer w10: J3.2@1848.27,3162.75 1913.27,3227.75 v1(2003.27,3227.76)
U1_6: R3.2 U1.6 | length 415.4
  Bottom Layer w10: v1(2124.77,2947.76) 2246.38,3069.37 v1@2246.38,3312.75
  other v1: 2246.38,3312.76
U1_7: R2.2 U1.7 | length 811.3
  Top Layer w10: R2.2@1932.28,2810.51 1969.27,2810.55 2059.87,2901.05 2185.07,2901.05 v1@2203.17,2919.15
  Bottom Layer w10: v1(2203.15,2919.17) 2288.27,3004.29 2288.27,3322.76 v1(2248.27,3362.76)
U2_5: TXAL1.1 U2.5 | length 485.5
  Top Layer w10: v1@2598.27,3162.75 2598.27,3167.75 2724.37,3293.85 U2.5@2724.37,3339.25 ; v1(2681.1,3034.92) TXAL1.1@2681.14,2940.43 TXAL1.1@2681.17,2940.45
  Bottom Layer w10: v1(2598.27,3162.76) 2598.27,3117.75 v1(2681.1,3034.92)
U2_6: TXAL1.3 U2.6 | length 490.8
  Top Layer w10: v1@2648.87,3164.05 2648.87,3193.35 2744.07,3288.55 U2.6@2744.07,3339.25 ; v1(2774.8,3035.71) 2775.57,3034.95 TXAL1.3@2775.57,2940.45
  Bottom Layer w10: v1(2648.82,3164.05) 2648.82,3161.69 v1(2774.8,3035.71)
U2_7: C3.1 R18.1 RESET.1 U2.7 | length 994.9
  Top Layer w10: v1@2698.47,3208.95 2763.77,3274.25 U2.7@2763.77,3339.25
  Bottom Layer w10: v1@2698.47,3208.95 3114.27,2793.05 3153.37,2793.05 3167.57,2778.85 C3.1@3167.57,2653.05 ; R18.1@3104.77,2727.75 RESET.1@3150.37,2773.35
  other v1: 2698.43,3208.93
U4_2: U4.2 U11.2 U12.1 | length 1866
  Top Layer w10: U12.1@4312.97,2606.55 4312.97,2856.55 4681.17,3224.75 U4.2@4681.17,3905.05 ; U4.2@4681.14,3905.07 4681.1,4034.95 4741.1,4094.85 U11.2@4741.09,4295.15
U4_3: U4.3 U11.3 U12.2 | length 1832.8
  Top Layer w10: U12.2@4412.97,2606.55 4412.97,2842.45 4712.67,3142.05 U4.3@4712.67,3905.05 ; U4.3@4712.64,3905.07 4712.6,4025.05 4760.8,4073.15 U11.3@4760.78,4295.15
U4_4: U4.4 U11.4 U12.3 | length 1799.4
  Top Layer w10: U12.3@4512.97,2606.55 4516.57,2610.15 4516.57,2834.95 4744.17,3062.55 U4.4@4744.17,3905.05 ; U4.4@4744.13,3905.07 4744.1,4017.95 4780.4,4054.25 U11.4@4780.4,4295.15
U4_5: U4.5 U11.5 U12.4 | length 1766.1
  Top Layer w10: U12.4@4612.97,2606.55 4612.97,2811.65 4775.67,2974.35 U4.5@4775.67,3905.05 ; U4.5@4775.63,3905.07 4775.6,4008.65 4800.1,4033.15 U11.5@4800.1,4295.15
U4_6: U4.6 U11.6 U12.5 | length 1732.7
  Top Layer w10: U12.5@4712.97,2606.55 4713.37,2800.25 4807.17,2894.05 U4.6@4807.17,3905.05 ; U4.6@4807.12,3905.07 4807.1,4005.35 4819.8,4018.05 U11.6@4819.83,4295.15
U4_7: U4.7 U11.7 U12.6 | length 1699.6
  Top Layer w10: U12.6@4812.97,2606.55 4812.97,2792.85 4838.67,2818.45 U4.7@4838.67,3905.05 ; U4.7@4838.62,3905.07 4838.6,4010.45 4839.51,4011.35 U11.7@4839.52,4295.15
U4_8: U4.8 U11.8 U12.7 | length 1710.9
  Top Layer w10: U11.8@4859.1,4295.15 4859.1,4013.35 4870.1,4002.35 U4.8@4870.12,3905.07 ; U4.8@4870.17,3905.05 4870.17,2815.95 4912.97,2773.05 U12.7@4912.97,2606.55
U4_9: U4.9 U11.9 U12.8 | length 1744.2
  Top Layer w10: U11.9@4878.8,4295.15 4878.8,4023.65 4901.6,4000.85 U4.9@4901.61,3905.07 ; U4.9@4901.57,3905.05 4901.57,2889.25 5012.97,2777.85 U12.8@5012.97,2606.55
U4_10: U4.10 U11.10 U12.9 | length 1777.4
  Top Layer w10: U11.10@4898.5,4295.15 4898.5,4033.95 4933.1,3999.35 U4.10@4933.11,3905.07 ; U4.10@4933.07,3905.05 4933.07,2966.45 5112.97,2786.55 U12.9@5112.97,2606.55
U4_11: U4.11 U11.11 U12.10 | length 1810.7
  Top Layer w10: U11.11@4918.2,4295.15 4918.2,4054.25 4964.51,4007.95 U4.11@4964.51,3905.05 ; U4.11@4964.57,3905.05 4964.57,3047.45 5210.97,2801.05 5210.97,2608.55 U12.10@5212.97,2606.55
U4_12: U4.12 U11.12 U12.11 | length 1843.9
  Top Layer w10: U11.12@4937.94,4295.15 4937.9,4069.55 4996,4011.45 U4.12@4996,3905.05 ; U4.12@4996.07,3905.05 4996.07,3131.75 5312.97,2814.85 U12.11@5312.97,2606.55
U4_13: U4.13 U11.13 U12.12 | length 1877.2
  Top Layer w10: U11.13@4957.63,4295.15 4957.6,4089.85 5027.5,4019.95 U4.13@5027.5,3905.05 ; U4.13@5027.57,3905.05 5027.57,3207.35 5412.97,2821.95 U12.12@5412.97,2606.55
USB1_2: R7.2 USB1.2 | length 177.7
  Top Layer w10: USB1.2@1901.81,3536.9 2035.87,3536.95 R7.2@2066.77,3567.75
USB1_3: R8.2 R9.2 USB1.3 | length 362.3
  Top Layer w10: USB1.3@1901.77,3511.25 2043.27,3511.25 R8.2@2066.77,3487.75 ; v1(2128.35,3642.79) 2128.35,3646.34 R9.2@2129.76,3647.75
  Bottom Layer w10: v1(2063.27,3487.76) 2063.27,3545.43 2128.35,3610.51 v1(2128.35,3642.79)
USB_DM: R7.1 U2.44 | length 943.4
  Top Layer w10: v1@2668.27,3612.75 2724.37,3668.85 U2.44@2724.37,3776.25
  Bottom Layer w10: v1@2128.27,3567.75 2093.27,3532.75 2093.27,3462.75 2293.17,3462.75 2443.17,3612.75 v1@2668.27,3612.75
  other v1: 2128.27,3567.76 2668.27,3612.76
USB_DP: R8.1 U2.45 | length 749.9
  Top Layer w10: v1@2668.27,3647.75 2704.67,3684.15 U2.45@2704.67,3776.25
  Bottom Layer w10: v1@2128.27,3487.75 2276.47,3487.75 2436.47,3647.75 v1@2668.27,3647.75
  other v1: 2128.27,3487.76 2668.27,3647.76
VCC_LCD: BUZZER1.1 C13.2 D4.2 H3.3 H3.4 H3.10 U7.3 | length 2472.5
  Top Layer w10: v1(2793.27,4272.76) 2823.27,4242.75 BUZZER1.1@2823.27,4187.75
  Bottom Layer w10: H3.3@1758.27,4367.75 H3.4@1758.27,4317.75 1723.27,4282.76 1723.27,4057.75 1758.27,4022.75 H3.10@1758.27,4017.75 1863.27,4122.75 2066.57,4122.75 2216.57,4272.75 2793.27,4272.75 2819.17,4298.65 3176.37,4298.65 ; BUZZER1.1@2823.27,4187.75 2823.27,4081.35 D4.2@2898.27,4006.35 ; C13.2@3176.37,4338.05 3176.37,4298.65 ; U7.3@3324.07,4151.85 3176.37,4299.55 3176.37,4298.65
VCC_MCU: C6.2 C7.2 C8.2 C9.2 C10.2 C11.1 C16.2 H1.2 P1.1 P2.1 P2.4 P3.1 P3.4 P4.1 P5.1 P6.1 P7.1 P8.1 P9.1 R10.2 R11.2 R14.1 R15.2 R18.2 RC5H.1 RC6H.1 RC7H.1 RC8H.1 RC9H.1 RC10H.1 RC11H.1 RC12H.1 RC13H.1 RC14H.1 RC15H.1 U2.13 U2.19 U2.32 U2.48 U2.64 U5.8 U9.3 U10.2 | length 13263.2
  Top Layer w10: P7.1@2028.87,2561.05 2043.27,2546.75 v1@2043.27,2407.75 ; v1(2073.27,4167.76) 2116.34,4124.68 v1(2194.49,4124.68) ; U5.8@2248.27,3180.63 2248.27,3204.25 2326.77,3282.75 2376.77,3332.75 2428.27,3332.75 2466.77,3294.25 R11.2@2466.77,3282.75 ; C6.2@2465.37,3381.35 2466.77,3379.95 R11.2@2466.77,3282.75 ; C8.2@2518.11,3777.43 2519.27,3776.25 U2.48@2645.67,3776.25 ; P8.1@2532.47,2563.55 2578.27,2517.75 v1@2578.27,2407.75 ; U2.64@2574.77,3410.11 2574.77,3390.75 2567.17,3383.15 R11.2@2466.77,3282.75 ; v1@2628.27,3982.75 2645.67,3965.35 U2.48@2645.67,3776.25 ; v1(2778.27,3517.76) 2768.27,3507.75 2678.27,3507.75 2633.27,3552.75 v1(2633.27,3692.76) 2633.27,3763.85 U2.48@2645.67,3776.25 ; v1@2833.27,3447.75 2881.87,3399.15 U2.13@2881.87,3339.25 ; P2.4@3015.1,2561.61 3015.07,2520.95 3043.27,2492.75 3128.27,2492.75 3162.77,2527.25 3162.77,2561.05 3464.97,2561.05 3539.97,2486.15 3596.57,2486.15 3644.77,2534.25 P3.4@3644.8,2561.61 3644.77,2526.25 3688.27,2482.75 3748.27,2482.75 3792.47,2526.95 3792.47,2561.05 3792.47,2626.95 3931.77,2766.25 v1(3931.78,2789.02) ; C9.2@3090.57,3877.45 3011.77,3798.65 3011.77,3705.35 3019.17,3712.75 v1@3148.27,3712.75 ; C9.2@3093.27,3877.75 3178.27,3877.75 v1@3528.27,4227.75 ; C7.2@3170.86,3353.03 3170.87,3364.05 3116.57,3418.35 3085.47,3449.45 3011.77,3449.45 3526.57,3449.45 3708.27,3267.75 v1@3708.27,3117.75 ; U10.2@3438.27,3087.75 3523.27,3087.75 v1(3548.27,3112.76) ; v1(3479.53,3944.25) 3479.53,4179.01 v1(3528.27,4227.76) ; v1(3931.78,2789.02) 3963.27,2820.51 3963.27,2902.75 v1(3963.27,2917.76) ; v1(4004.25,4298.3) v1(4004.25,4455.78) 3878.77,4455.75 3849.97,4426.95 3667.47,4426.95 3528.27,4287.75 v1@3528.27,4227.75
  Bottom Layer w10: RC12H.1@1883.77,2406.75 1933.57,2356.95 1991.47,2356.95 2041.27,2406.75 2091.07,2356.95 2381.17,2356.95 2424.47,2400.45 RC14H.1@2424.37,2408.95 ; H1.2@1973.27,4652.75 1923.27,4602.75 1923.27,4452.75 1923.27,4317.75 v1(2073.27,4167.76) ; P1.1@2048.27,3742.75 2098.27,3692.75 v1@2633.27,3692.75 ; R14.1@2176.38,4023.11 2180.37,4027.05 2255.17,4027.05 2284.27,4056.15 C11.1@2284.27,4111.25 ; R15.2@2194.47,4124.65 2270.87,4124.65 C11.1@2284.27,4111.25 ; RC14H.1@2423.27,2411.25 2477.57,2356.95 2515.47,2356.95 2569.77,2411.25 2580.77,2411.25 2732.27,2562.75 v1@3018.27,2562.75 ; v1(2567.2,3383.19) 2606.77,3422.75 2808.27,3422.75 v1(2833.27,3447.76) 2778.27,3502.75 v1(2778.27,3517.76) ; v1@2628.27,3982.75 2412.77,3982.75 C11.1@2284.27,4111.25 ; v1@2829.43,3443.91 2898.27,3512.76 3022.16,3512.76 v1(3116.54,3418.38) 3116.54,3681.03 v1(3148.27,3712.76) ; v1@3012.57,2562.75 2943.27,2632.05 2943.27,2677.75 2993.27,2727.75 R18.2@3041.77,2727.75 ; v1@3093.27,3877.75 3033.27,3877.75 3028.27,3882.75 3028.27,4078.75 U9.3@3096.37,4146.85 ; C16.2@3420.47,4338.05 3528.27,4230.25 v1@3528.27,4227.75 ; RC7H.1@3479.57,3944.25 3511.07,3912.75 3605.47,3912.75 v1(3637.01,3944.25) 3668.47,3912.75 3823.27,3912.75 3833.27,3922.75 v1@3853.27,3922.75 ; RC6H.1@3551.81,3116.24 3583.27,3147.75 3677.77,3147.75 RC5H.1@3709.29,3116.24 ; v1@3847.47,3431.95 3873.27,3406.15 3873.27,3177.75 3811.77,3116.25 RC5H.1@3709.29,3116.24 ; v1(3849.95,2916.94) 3860.77,2927.75 3953.27,2927.75 v1(3963.27,2917.76) v1@3963.27,2922.75 ; v1(3931.78,2789.02) 3709.27,3011.55 RC5H.1@3709.29,3116.24
  other v1: 2043.27,2407.76 2578.27,2407.76 3012.53,2562.76 3708.27,3117.76 3847.45,3431.94 3093.27,3877.76 3853.27,3922.76 2628.27,3982.76
VCC_NRF: C14.2 U6.2 U8.3 | length 2019.9
  Top Layer w10: v1(3308.27,3362.76) 3363.27,3417.75 3513.27,3417.75 3563.27,3367.75 v1(3563.27,3362.76)
  Bottom Layer w10: U6.2@3208.27,3363.45 3208.97,3362.75 v1@3308.27,3362.75 ; C14.2@3259.07,4338.05 3303.27,4293.85 3303.27,4292.75 3323.27,4272.75 3418.27,4272.75 3539.17,4151.85 3551.37,4151.85 3744.17,4151.85 3958.27,3937.75 3956.27,3935.75 U6.2@3956.3,3735.51 3936.07,3735.55 v1@3563.27,3362.75
VM: R16.2 R17.1 U2.25 | length 1415.2
  Top Layer w10: R17.1@3240.87,3097.75 R16.2@3240.87,3182.75 ; v1@3443.27,3557.75 3443.27,3562.75 v1@3438.27,3567.75 ; U2.25@3011.97,3567.75 3011.77,3567.55 U2.25@3011.97,3567.75 ; U2.25@3011.97,3567.75 v1@3438.27,3567.75 ; U2.25@3011.97,3567.75 v1@3438.27,3567.75
  Bottom Layer w10: v1(3238.27,3182.76) 3443.27,3387.75 v1(3443.27,3562.76)
pads on no net: CN1.0 CN2.0 CN3.0 P2.0 P3.0 P4.0 P5.0 P6.0 P7.0 P8.0 P9.0 SW2.6 SW2.7 TP1.1 TP2.1 TP3.1 TP4.1 TP5. TP6. TP7. TP8. TP9. TP10. TP11. TP12. U2.1 U4.1 U4.14 U11.1 U11.14 U11.15 U11.16 USB1. USB1.6 USB1.7 USB1.8 USB1.9

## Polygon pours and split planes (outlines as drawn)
GND on Top Layer (solid): 4102.36,2282.16 4102.36,4804.21 4066.14,4840.43 1553.54,4840.43 1500,4893.97 1500,2264.05 1519.68,2244.37
GND on Bottom Layer (solid): 4102.36,2259.33 4102.36,4781.37 4056.69,4827.04 1588.19,4827.04 1514.96,4753.81 1514.96,2357.75 1614.96,2257.75

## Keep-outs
Keep-Out Layer:
  lines w10: 1688.19,2397.91 ccw(c1766.93,2397.91) 1766.93,2319.17 ; 1688.19,4680.59 cw(c1766.93,4680.59) 1766.93,4759.33 ; 4432.28,1583.74 ccw(c4511.02,1583.74) 4511.02,1505 ; 5499.2,1505 ccw(c5499.2,1583.74) 5577.94,1583.74 ; 5499.21,4759.32 cw(c5499.21,4680.58) 5577.95,4680.58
